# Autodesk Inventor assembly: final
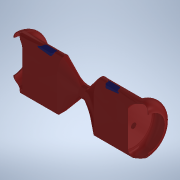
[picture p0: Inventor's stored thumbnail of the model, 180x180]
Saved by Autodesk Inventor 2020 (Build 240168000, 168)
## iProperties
Created: 2017-04
Part Number: final
Document SubType Name: Assembly
Designer: bruno
Sending System: SolidWorks 2016
Last Author: Samartha
Last Saved: 2017-04-03
Author: bruno
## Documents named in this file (3)
- C:\Users\bruno\Documents\1-Cours-2022-23\1SI\2. Cinématique\Hoverboard\Inventor-Hoverboard\final.iam
- C:\Users\bruno\Documents\1-Cours-2022-23\1SI\2. Cinématique\Hoverboard\Inventor-Hoverboard\body.ipt
- C:\Users\bruno\Documents\1-Cours-2022-23\1SI\2. Cinématique\Hoverboard\Inventor-Hoverboard\pad.ipt
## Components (3 placed, 2 different names)
1. body:1
2. pad:1
3. pad:2
